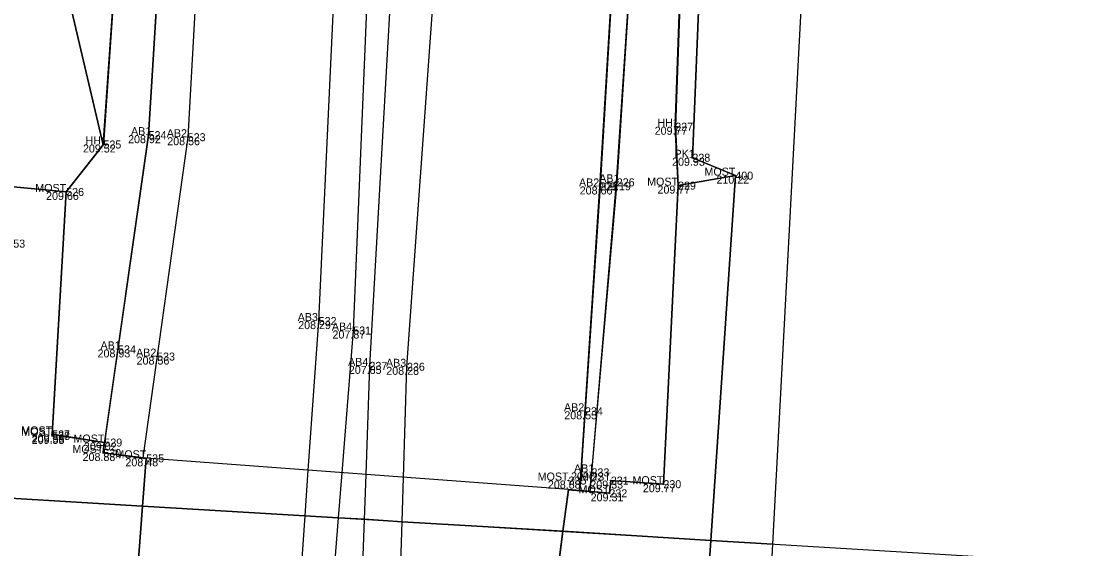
# Model space of a CAD drawing. Extents: x -262982 to -262706, y -1238714 to -1237093.
# Drawn here: x -262835.54 to -262808.76, y -1237934.9 to -1237921.73 of the extents above; entities that cross this region are included whole.
import ezdxf

# ---------------------------------------------------------------- set-up
doc = ezdxf.new("R2010")
doc.units = 0
for name, color, linetype in [('01_Hrana_betónu', 7, 'Continuous'), ('02_Oplotenie', 7, 'Continuous'), ('03_Asfalt', 7, 'Continuous'), ('04_Most', 7, 'Continuous'), ('05_Hrana_terénu', 7, 'Continuous'), ('09_Múrik', 7, 'Continuous'), ('10', 7, 'Continuous'), ('Groma (21)', 7, 'Continuous'), ('Groma (22)', 7, 'Continuous'), ('Groma (23)', 7, 'Continuous'), ('Groma (24)', 7, 'Continuous'), ('U003_Asfalt', 7, 'Continuous'), ('U003_Betónové_panely', 7, 'Continuous'), ('U003_Ostatné_plochy', 7, 'Continuous'), ('U004_Asfalty', 7, 'Continuous'), ('U004_Betónové_múriky', 7, 'Continuous'), ('U004_Betónové_panely', 7, 'Continuous'), ('U004_Ostatné_plochy', 7, 'Continuous'), ('U004_Zeleň_mimo', 7, 'Continuous'), ('U004_Zeleň_vnútro', 7, 'Continuous'), ('U004_Zeleň_zatrávňovač', 7, 'Continuous')]:
    doc.layers.add(name, color=color, linetype=linetype)

msp = doc.modelspace()

# ---------------------------------------------------------------- linework, layer by layer
at = {"layer": '01_Hrana_betónu'}
for p, q in [((-262832.416, -1237932.646), (-262832.51, -1237933.84)), ((-262822, -1237934.47), (-262821.859, -1237933.429)), ((-262832.51, -1237933.84), (-262832.64, -1237935.62)), ((-262822.231, -1237936.276), (-262822, -1237934.47))]:
    msp.add_line(p, q, dxfattribs=at)
for points in [[(-262833.49, -1237932.513), (-262832.358, -1237924.572), (-262831.993, -1237918.626), (-262831.904, -1237915.074), (-262831.439, -1237906.309), (-262830.324, -1237884.482), (-262828.859, -1237869.656), (-262826.973, -1237856.487), (-262824.752, -1237845.872), (-262820.768, -1237827.409), (-262815.971, -1237805.011), (-262811.874, -1237785.528), (-262810.073, -1237767.205), (-262809.465, -1237744.209), (-262809.348, -1237719.32), (-262807.762, -1237709.127), (-262805.583, -1237701.261), (-262801.096, -1237689.829), (-262795.064, -1237676.268)], [(-262794.181, -1237676.612), (-262800.21, -1237690.201), (-262804.735, -1237701.618), (-262806.814, -1237709.415), (-262808.46, -1237719.391), (-262808.589, -1237744.23), (-262809.169, -1237767.262), (-262810.977, -1237785.858), (-262815.119, -1237805.286), (-262819.878, -1237827.449), (-262823.898, -1237846.237), (-262826.14, -1237856.747), (-262827.996, -1237869.725), (-262829.453, -1237884.611), (-262830.572, -1237906.318), (-262830.909, -1237915.064), (-262831.044, -1237918.638), (-262831.379, -1237924.623), (-262832.499, -1237932.636), (-262832.416, -1237932.646)], [(-262828.366, -1237932.946), (-262828.106, -1237929.217), (-262827.649, -1237919.578), (-262827.369, -1237915.073), (-262826.968, -1237906.664), (-262825.835, -1237884.909), (-262824.318, -1237870.338), (-262822.252, -1237856.88), (-262820.394, -1237847.242), (-262816.344, -1237828.005), (-262811.527, -1237806.128), (-262807.485, -1237786.652), (-262805.817, -1237767.526), (-262804.904, -1237743.876), (-262804.544, -1237721.54), (-262802.773, -1237710.111), (-262800.948, -1237703.699), (-262796.578, -1237692.416), (-262790.297, -1237678.834), (-262789.671, -1237677.512)], [(-262788.862, -1237677.903), (-262789.612, -1237679.5), (-262795.758, -1237692.783), (-262800.102, -1237704.105), (-262801.904, -1237710.319), (-262803.638, -1237721.631), (-262804.041, -1237743.855), (-262804.886, -1237767.666), (-262806.567, -1237786.84), (-262810.653, -1237806.707), (-262815.575, -1237828.361), (-262819.614, -1237847.41), (-262821.404, -1237856.927), (-262823.638, -1237870.532), (-262825.083, -1237884.947), (-262826.299, -1237906.725), (-262827.242, -1237929.453), (-262827.527, -1237933.008)], [(-262788.441, -1237678.106), (-262789.499, -1237680.304), (-262796.488, -1237695.789), (-262799.561, -1237704.378), (-262801.599, -1237711.648), (-262803.17, -1237722.277), (-262803.523, -1237744.912), (-262804.331, -1237767.555), (-262806.033, -1237786.907), (-262810.428, -1237808.027), (-262815.321, -1237829.941), (-262818.5, -1237845.545), (-262820.865, -1237857.635), (-262822.962, -1237871.266), (-262824.386, -1237885.795), (-262825.49, -1237906.658), (-262826.835, -1237930.337), (-262826.931, -1237933.053)], [(-262825.987, -1237933.123), (-262825.899, -1237930.36), (-262825.137, -1237919.703), (-262824.89, -1237915.193), (-262824.65, -1237906.715), (-262823.596, -1237885.855), (-262822.137, -1237871.403), (-262820.061, -1237857.781), (-262817.692, -1237845.812), (-262814.459, -1237830.149), (-262809.645, -1237808.205), (-262805.191, -1237787.117), (-262803.484, -1237767.641), (-262802.568, -1237744.998), (-262802.266, -1237722.317), (-262800.862, -1237712.121), (-262798.805, -1237704.616), (-262795.791, -1237696.17), (-262788.393, -1237679.964), (-262787.674, -1237678.477)], [(-262828.445, -1237934.083), (-262828.366, -1237932.946)], [(-262827.527, -1237933.008), (-262827.618, -1237934.133)], [(-262826.931, -1237933.053), (-262826.971, -1237934.173)], [(-262826.022, -1237934.23), (-262825.987, -1237933.123)], [(-262828.571, -1237935.876), (-262828.445, -1237934.083)], [(-262827.618, -1237934.133), (-262827.762, -1237935.927)], [(-262826.971, -1237934.173), (-262827.034, -1237935.973)], [(-262826.079, -1237936.033), (-262826.022, -1237934.23)]]:
    msp.add_lwpolyline(points, dxfattribs=at)
at = {"layer": '02_Oplotenie'}
msp.add_lwpolyline([(-262782.476, -1237683.046), (-262789.338, -1237700.035), (-262791.92, -1237707.468), (-262793.68, -1237714.792), (-262794.853, -1237723.195), (-262795.698, -1237745.299), (-262796.564, -1237768.081), (-262798.719, -1237788.188), (-262802.852, -1237809.448), (-262807.527, -1237831.589), (-262810.764, -1237846.834), (-262812.842, -1237857.763), (-262814.888, -1237871.127), (-262816.319, -1237886.182), (-262816.945, -1237895.233), (-262817.687, -1237906.993), (-262818.366, -1237915.571), (-262818.764, -1237925.136)], dxfattribs=at)
at = {"layer": '03_Asfalt'}
for points in [[(-262814.5, -1237895.481), (-262815.119, -1237905.177), (-262816.001, -1237920.483), (-262816.76, -1237934.791)], [(-262816.76, -1237934.791), (-262817.067, -1237940.584), (-262818.198, -1237960.603), (-262819.351, -1237980.318), (-262820.259, -1237997.242), (-262821.106, -1238014.516), (-262822.726, -1238037.787), (-262824.929, -1238056.475), (-262826.695, -1238065.295), (-262832.135, -1238081.046), (-262834.142, -1238085.994), (-262836.111, -1238090.171)]]:
    msp.add_lwpolyline(points, dxfattribs=at)
at = {"layer": '04_Most'}
for points in [[(-262818.304, -1237934.697), (-262817.69, -1237925.584), (-262819.123, -1237925.833), (-262819.489, -1237933.293), (-262820.803, -1237933.203), (-262820.839, -1237933.52), (-262821.859, -1237933.429), (-262832.416, -1237932.646), (-262833.49, -1237932.513), (-262833.464, -1237932.253), (-262834.768, -1237932.047), (-262834.418, -1237925.991), (-262837.149, -1237925.733), (-262837.354, -1237927.143), (-262835.889, -1237927.282), (-262836.391, -1237933.13), (-262837.42, -1237933.072), (-262837.476, -1237933.537)], [(-262837.476, -1237933.537), (-262837.588, -1237934.475), (-262836.324, -1237934.594), (-262836.292, -1237935.17), (-262835.062, -1237935.275), (-262834.664, -1237935.731), (-262834.562, -1237935.803), (-262833.682, -1237935.77), (-262833.657, -1237935.467), (-262832.64, -1237935.62), (-262822.231, -1237936.276), (-262821.226, -1237936.393), (-262821.088, -1237936.694), (-262819.91, -1237936.875), (-262819.871, -1237937.657), (-262818.511, -1237937.77), (-262818.304, -1237934.697)]]:
    msp.add_lwpolyline(points, dxfattribs=at)
at = {"layer": '05_Hrana_terénu'}
for points in [[(-262819.123, -1237925.833), (-262819.193, -1237924.361), (-262818.874, -1237915.472), (-262818.289, -1237906.84), (-262817.033, -1237886.241), (-262815.506, -1237871.209), (-262813.693, -1237857.604), (-262811.493, -1237846.649), (-262808.389, -1237831.401), (-262803.328, -1237809.401), (-262799.108, -1237788.219), (-262797.264, -1237767.972), (-262796.32, -1237745.233), (-262795.609, -1237723.113), (-262794.587, -1237714.488), (-262792.775, -1237707.13), (-262790.198, -1237699.936), (-262783.238, -1237683.427), (-262781.933, -1237681.667), (-262781.499, -1237681.254)], [(-262833.13, -1237919.565), (-262833.486, -1237924.805), (-262834.418, -1237925.991)]]:
    msp.add_lwpolyline(points, dxfattribs=at)
at = {"layer": '09_Múrik'}
for points in [[(-262819.991, -1237915.564), (-262820.655, -1237925.75), (-262821.327, -1237933.476)], [(-262821.581, -1237933.453), (-262821.074, -1237925.854), (-262820.488, -1237916.085)]]:
    msp.add_lwpolyline(points, dxfattribs=at)
at = {"layer": '10'}
msp.add_line((-262851.323, -1237932.698), (-262791.061, -1237936.346), dxfattribs=at)
at = {"layer": 'Groma (21)'}
for centre in [(-262819.193, -1237924.361), (-262832.358, -1237924.572), (-262831.379, -1237924.623), (-262833.486, -1237924.805), (-262818.764, -1237925.136), (-262820.655, -1237925.75), (-262817.69, -1237925.584), (-262834.418, -1237925.991), (-262821.074, -1237925.854), (-262819.123, -1237925.833), (-262828.106, -1237929.217), (-262827.242, -1237929.453), (-262833.121, -1237929.925), (-262832.145, -1237930.104), (-262826.835, -1237930.337), (-262825.899, -1237930.36), (-262821.449, -1237931.471), (-262834.768, -1237932.047), (-262834.767, -1237932.086), (-262833.464, -1237932.253), (-262833.49, -1237932.513), (-262832.416, -1237932.646), (-262821.859, -1237933.202), (-262821.285, -1237932.998), (-262820.803, -1237933.203), (-262820.839, -1237933.52), (-262819.489, -1237933.293)]:
    msp.add_circle(centre, 0.01, dxfattribs=at)
at = {"layer": 'U003_Asfalt'}
msp.add_lwpolyline([(-262818.51, -1237937.77), (-262818.3, -1237934.7), (-262816.76, -1237934.79), (-262817.07, -1237940.58)], dxfattribs=at)
at = {"layer": 'U003_Betónové_panely'}
msp.add_lwpolyline([(-262832.64, -1237935.62), (-262832.51, -1237933.84), (-262828.45, -1237934.08), (-262827.62, -1237934.13), (-262826.97, -1237934.17), (-262826.02, -1237934.23), (-262822, -1237934.47), (-262822.23, -1237936.28)], dxfattribs=at)
at = {"layer": 'U003_Ostatné_plochy'}
for points in [[(-262832.51, -1237933.84), (-262832.64, -1237935.62), (-262833.66, -1237935.47), (-262833.68, -1237935.77), (-262834.56, -1237935.8), (-262834.66, -1237935.73), (-262835.06, -1237935.28), (-262836.29, -1237935.17), (-262836.32, -1237934.59), (-262837.59, -1237934.48), (-262837.48, -1237933.54)], [(-262818.3, -1237934.7), (-262818.51, -1237937.77), (-262819.87, -1237937.66), (-262819.91, -1237936.88), (-262821.09, -1237936.69), (-262821.23, -1237936.39), (-262822.23, -1237936.28), (-262822, -1237934.47)]]:
    msp.add_lwpolyline(points, close=True, dxfattribs=at)
at = {"layer": 'U004_Asfalty'}
msp.add_lwpolyline([(-262818.76, -1237925.14), (-262818.37, -1237915.57), (-262817.69, -1237906.99), (-262816.95, -1237895.23), (-262814.5, -1237895.48), (-262815.12, -1237905.18), (-262816, -1237920.48), (-262816.76, -1237934.79), (-262818.3, -1237934.7), (-262817.69, -1237925.58)], close=True, dxfattribs=at)
at = {"layer": 'U004_Betónové_múriky'}
msp.add_lwpolyline([(-262820.66, -1237925.75), (-262821.33, -1237933.48), (-262821.58, -1237933.45), (-262821.07, -1237925.85), (-262820.49, -1237916.09), (-262819.99, -1237915.56)], close=True, dxfattribs=at)
at = {"layer": 'U004_Betónové_panely'}
msp.add_lwpolyline([(-262815.44, -1237858.03), (-262817.52, -1237871.5), (-262819.01, -1237885.89), (-262819.76, -1237906.84), (-262819.99, -1237915.56), (-262820.49, -1237916.09), (-262821.07, -1237925.85), (-262821.58, -1237933.45), (-262821.86, -1237933.43), (-262822, -1237934.47), (-262826.02, -1237934.23), (-262826.97, -1237934.17), (-262827.62, -1237934.13), (-262828.45, -1237934.08), (-262832.51, -1237933.84), (-262832.42, -1237932.65), (-262832.5, -1237932.64), (-262833.49, -1237932.51), (-262832.36, -1237924.57), (-262831.99, -1237918.63), (-262831.9, -1237915.07), (-262831.44, -1237906.31), (-262830.32, -1237884.48), (-262828.86, -1237869.66)], dxfattribs=at)
at = {"layer": 'U004_Ostatné_plochy'}
for points in [[(-262837.48, -1237933.54), (-262837.42, -1237933.07), (-262836.39, -1237933.13), (-262835.89, -1237927.28), (-262837.35, -1237927.14), (-262837.15, -1237925.73), (-262834.42, -1237925.99), (-262834.77, -1237932.05), (-262833.46, -1237932.25), (-262833.49, -1237932.51), (-262832.42, -1237932.65), (-262832.51, -1237933.84)], [(-262818.3, -1237934.7), (-262822, -1237934.47), (-262821.86, -1237933.43), (-262820.84, -1237933.52), (-262820.8, -1237933.2), (-262819.49, -1237933.29), (-262819.12, -1237925.83), (-262817.69, -1237925.58)]]:
    msp.add_lwpolyline(points, close=True, dxfattribs=at)
at = {"layer": 'U004_Zeleň_mimo'}
msp.add_lwpolyline([(-262831.15, -1237869.34), (-262832.73, -1237884.62), (-262833.81, -1237906.28), (-262834.02, -1237915.3), (-262834.34, -1237921.2), (-262833.49, -1237924.81), (-262834.42, -1237925.99), (-262837.15, -1237925.73), (-262837.41, -1237925.56), (-262839.28, -1237924.72), (-262838.95, -1237919.22), (-262848.49, -1237918.39), (-262860.57, -1237917.21), (-262859.39, -1237895.81), (-262865.89, -1237895.46), (-262864.07, -1237848.35)], dxfattribs=at)
at = {"layer": 'U004_Zeleň_vnútro'}
for points in [[(-262798.72, -1237788.19), (-262802.85, -1237809.45), (-262807.53, -1237831.59), (-262810.76, -1237846.83), (-262812.84, -1237857.76), (-262814.89, -1237871.13), (-262816.32, -1237886.18), (-262816.95, -1237895.23), (-262817.69, -1237906.99), (-262818.37, -1237915.57), (-262818.76, -1237925.14), (-262817.69, -1237925.58), (-262819.12, -1237925.83), (-262819.19, -1237924.36), (-262818.87, -1237915.47), (-262818.29, -1237906.84), (-262817.03, -1237886.24), (-262815.51, -1237871.21), (-262813.69, -1237857.6), (-262811.49, -1237846.65), (-262808.39, -1237831.4), (-262803.33, -1237809.4), (-262799.11, -1237788.22)], [(-262817.05, -1237804.55), (-262821.96, -1237827.47), (-262825.89, -1237845.54), (-262828.44, -1237856.36), (-262830.09, -1237869.52), (-262831.5, -1237884.45), (-262832.7, -1237906.27), (-262832.89, -1237914.23), (-262832.97, -1237914.84), (-262833.88, -1237915.77), (-262833.98, -1237919.36), (-262833.13, -1237919.57), (-262833.49, -1237924.81), (-262834.34, -1237921.2), (-262834.02, -1237915.3), (-262833.81, -1237906.28), (-262832.73, -1237884.62), (-262831.15, -1237869.34), (-262829.25, -1237856.33), (-262826.95, -1237845.31), (-262823.09, -1237827.73), (-262817.95, -1237804.34)]]:
    msp.add_lwpolyline(points, dxfattribs=at)
at = {"layer": 'U004_Zeleň_zatrávňovač'}
msp.add_lwpolyline([(-262813.69, -1237857.6), (-262815.51, -1237871.21), (-262817.03, -1237886.24), (-262818.29, -1237906.84), (-262818.87, -1237915.47), (-262819.19, -1237924.36), (-262819.12, -1237925.83), (-262819.49, -1237933.29), (-262820.8, -1237933.2), (-262820.84, -1237933.52), (-262821.33, -1237933.48), (-262821.28, -1237933), (-262820.66, -1237925.75), (-262819.99, -1237915.56), (-262819.76, -1237906.84), (-262819.01, -1237885.89), (-262817.52, -1237871.5), (-262815.44, -1237858.03)], dxfattribs=at)
msp.add_lwpolyline([(-262834.42, -1237925.99), (-262833.49, -1237924.81), (-262833.13, -1237919.57), (-262831.99, -1237918.63), (-262832.36, -1237924.57), (-262833.46, -1237932.25), (-262834.77, -1237932.05)], close=True, dxfattribs=at)

# ---------------------------------------------------------------- texts
at = {"layer": 'Groma (22)'}
for s, p in [('227', (-262819.193, -1237924.461)), ('524', (-262832.358, -1237924.672)), ('523', (-262831.379, -1237924.723)), ('525', (-262833.486, -1237924.905)), ('228', (-262818.764, -1237925.236)), ('400', (-262817.69, -1237925.684)), ('225', (-262821.074, -1237925.954)), ('226', (-262820.655, -1237925.85)), ('229', (-262819.123, -1237925.933)), ('526', (-262834.418, -1237926.091)), ('553', (-262835.889, -1237927.382)), ('532', (-262828.106, -1237929.317)), ('531', (-262827.242, -1237929.553)), ('534', (-262833.121, -1237930.025)), ('533', (-262832.145, -1237930.204)), ('237', (-262826.835, -1237930.437)), ('236', (-262825.899, -1237930.46)), ('234', (-262821.449, -1237931.571)), ('527', (-262834.768, -1237932.147)), ('528', (-262834.767, -1237932.186)), ('529', (-262833.464, -1237932.353)), ('530', (-262833.49, -1237932.613)), ('535', (-262832.416, -1237932.746)), ('233', (-262821.285, -1237933.098)), ('235', (-262821.859, -1237933.302)), ('231', (-262820.803, -1237933.303)), ('230', (-262819.489, -1237933.393)), ('232', (-262820.839, -1237933.62))]:
    msp.add_text(s, height=0.2, dxfattribs=at).set_placement(p)
at = {"layer": 'Groma (23)'}
for s, p in [('209.77', (-262819.706, -1237924.561)), ('208.92', (-262832.87, -1237924.772)), ('208.56', (-262831.891, -1237924.823)), ('209.52', (-262833.998, -1237925.005)), ('209.93', (-262819.271, -1237925.336)), ('209.19', (-262821.119, -1237925.95)), ('210.22', (-262818.163, -1237925.784)), ('209.66', (-262834.92, -1237926.191)), ('208.66', (-262821.581, -1237926.054)), ('209.77', (-262819.636, -1237926.033)), ('208.29', (-262828.618, -1237929.417)), ('207.87', (-262827.76, -1237929.653)), ('208.93', (-262833.633, -1237930.125)), ('208.56', (-262832.657, -1237930.304)), ('207.85', (-262827.352, -1237930.537)), ('208.28', (-262826.416, -1237930.56)), ('208.55', (-262821.966, -1237931.671)), ('209.58', (-262835.28, -1237932.247)), ('209.53', (-262835.279, -1237932.286)), ('209.02', (-262833.975, -1237932.453)), ('208.88', (-262834.007, -1237932.713)), ('208.48', (-262832.937, -1237932.846)), ('208.88', (-262822.376, -1237933.402)), ('209.22', (-262821.797, -1237933.198)), ('209.33', (-262821.315, -1237933.403)), ('209.31', (-262821.307, -1237933.72)), ('209.77', (-262820.002, -1237933.493))]:
    msp.add_text(s, height=0.2, dxfattribs=at).set_placement(p)
at = {"layer": 'Groma (24)'}
for s, p in [('AB1', (-262832.796, -1237924.572)), ('HH1', (-262819.64, -1237924.361)), ('HH1', (-262833.933, -1237924.805)), ('AB2', (-262831.903, -1237924.623)), ('PK1', (-262819.211, -1237925.136)), ('MOST', (-262818.462, -1237925.584)), ('AB2', (-262821.598, -1237925.854)), ('AB1', (-262821.093, -1237925.75)), ('MOST', (-262819.895, -1237925.833)), ('MOST', (-262835.19, -1237925.991)), ('AB3', (-262828.63, -1237929.217)), ('AB4', (-262827.776, -1237929.453)), ('AB1', (-262833.559, -1237929.925)), ('AB2', (-262832.669, -1237930.104)), ('AB4', (-262827.369, -1237930.337)), ('AB3', (-262826.423, -1237930.36)), ('AB2', (-262821.973, -1237931.471)), ('MOST', (-262835.54, -1237932.047)), ('MOST', (-262835.539, -1237932.086)), ('MOST', (-262834.236, -1237932.253)), ('MOST', (-262834.262, -1237932.513)), ('MOST', (-262833.188, -1237932.646)), ('AB1', (-262821.723, -1237932.998)), ('MOST', (-262822.631, -1237933.202)), ('MOST', (-262821.575, -1237933.203)), ('MOST', (-262820.261, -1237933.293)), ('MOST', (-262821.611, -1237933.52))]:
    msp.add_text(s, height=0.2, dxfattribs=at).set_placement(p)

doc.saveas('drawing.dxf')
